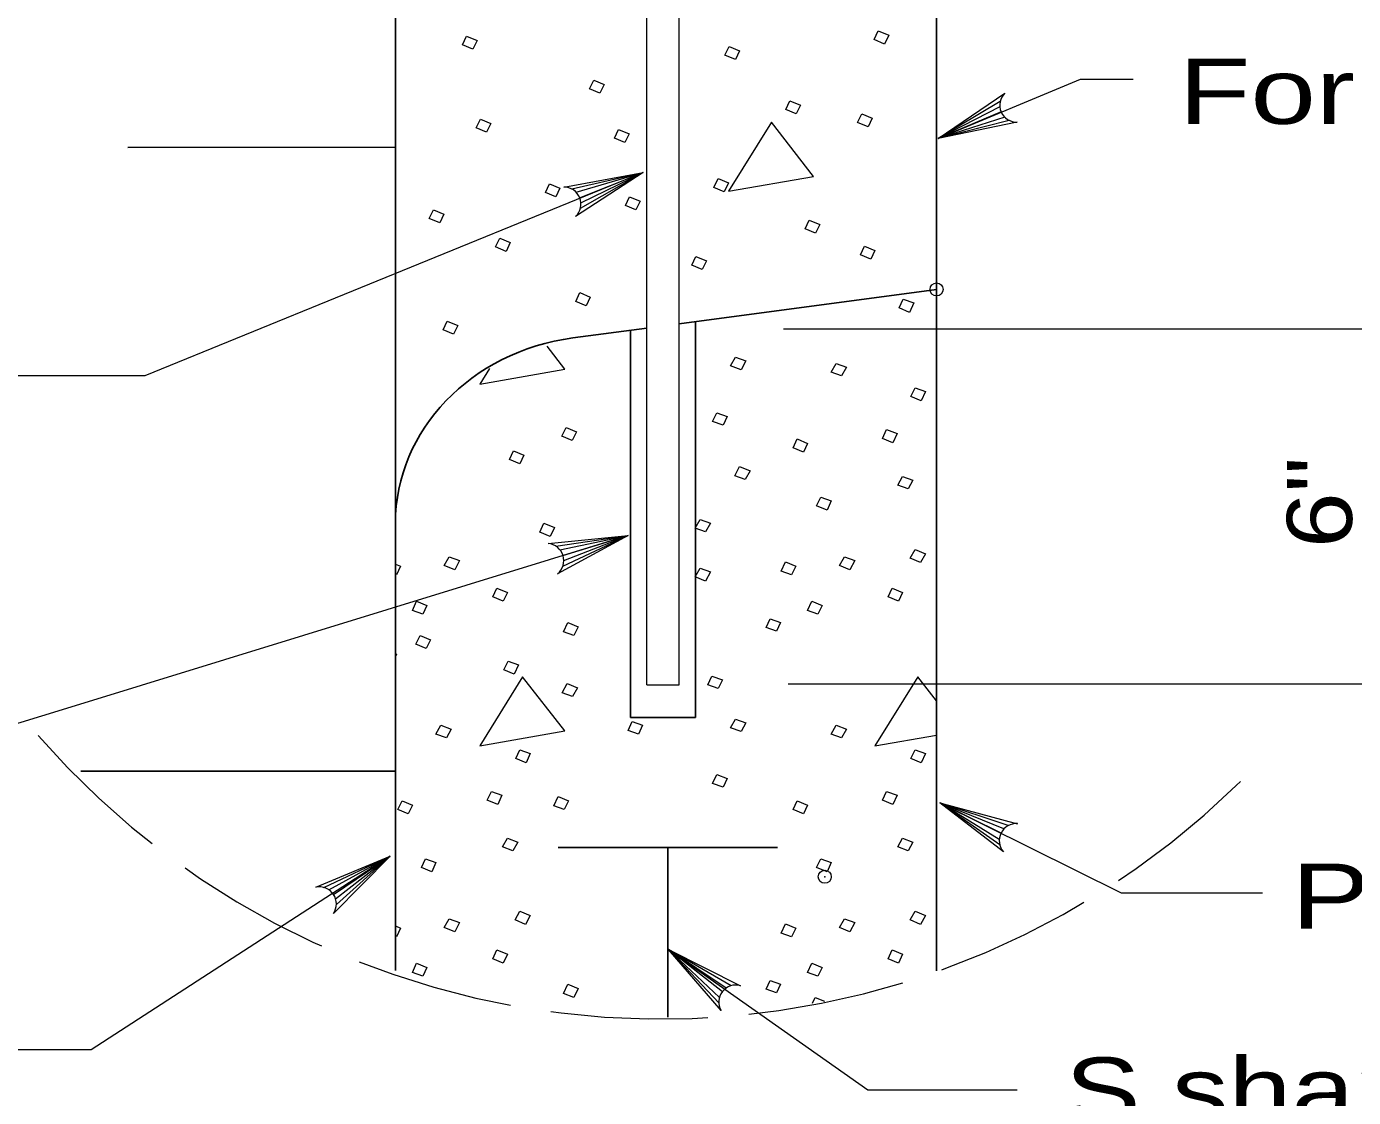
# Model space of a CAD drawing. Extents: x -1431.2 to -1397.2, y -1045.1 to -1001.1.
# Drawn here: x -1416.061 to -1412.824, y -1035.128 to -1032.516 of the extents above; entities that cross this region are included whole.
import ezdxf
from ezdxf.enums import TextEntityAlignment as Align

# ---------------------------------------------------------------- set-up
doc = ezdxf.new("R2010")
doc.units = 0
doc.header["$LTSCALE"] = 0.064
doc.header["$PDMODE"] = 32
doc.header["$PDSIZE"] = 0.032
doc.linetypes.add('LONG_DASHED', pattern=[7.5, 6, -1.5])
doc.layers.add('1', color=7, linetype='Continuous', lineweight=13)

msp = doc.modelspace()

# ---------------------------------------------------------------- linework, layer by layer
at = {"layer": '1'}
for p, q in [((-1414.54825, -1034.12175), (-1414.54825, -1031.64908)), ((-1414.46883, -1034.12175), (-1414.46883, -1031.64908)), ((-1413.84108, -1032.48925), (-1413.84108, -1033.15717)), ((-1413.68608, -1032.6985), (-1413.83692, -1032.78933)), ((-1413.68675, -1032.71192), (-1413.83692, -1032.78933)), ((-1413.68358, -1032.724), (-1413.83692, -1032.78933)), ((-1413.67458, -1032.73717), (-1413.83692, -1032.78933)), ((-1413.66408, -1032.74492), (-1413.83692, -1032.78933)), ((-1414.73092, -1032.91208), (-1414.55708, -1032.87167)), ((-1414.7205, -1032.92008), (-1414.55708, -1032.87167)), ((-1414.71183, -1032.9335), (-1414.55708, -1032.87167)), ((-1414.70992, -1032.959), (-1414.55708, -1032.87167)), ((-1414.70892, -1032.94558), (-1414.55708, -1032.87167)), ((-1414.21442, -1033.2535), (-1412.70433, -1033.2535)), ((-1414.59308, -1033.75767), (-1415.974, -1034.18242)), ((-1414.76967, -1033.78342), (-1414.59308, -1033.75767)), ((-1414.76, -1033.79225), (-1414.59308, -1033.75767)), ((-1414.75267, -1033.83192), (-1414.59308, -1033.75767)), ((-1414.75242, -1033.80633), (-1414.59308, -1033.75767)), ((-1414.75058, -1033.81867), (-1414.59308, -1033.75767)), ((-1413.84108, -1034.16075), (-1413.88692, -1034.10183)), ((-1414.54825, -1034.12175), (-1414.46883, -1034.12175)), ((-1414.20317, -1034.119), (-1412.70433, -1034.119)), ((-1413.68392, -1034.48342), (-1413.83317, -1034.40933)), ((-1413.68817, -1034.49883), (-1413.83317, -1034.40933)), ((-1413.68717, -1034.51192), (-1413.83317, -1034.40933)), ((-1413.67683, -1034.47317), (-1413.83317, -1034.40933)), ((-1413.66617, -1034.465), (-1413.83317, -1034.40933)), ((-1415.33558, -1034.616), (-1415.17425, -1034.53983)), ((-1415.32375, -1034.62167), (-1415.17425, -1034.53983)), ((-1415.31242, -1034.63292), (-1415.17425, -1034.53983)), ((-1415.30708, -1034.64417), (-1415.17425, -1034.53983)), ((-1415.30517, -1034.6575), (-1415.17425, -1034.53983)), ((-1414.36367, -1034.87025), (-1414.495, -1034.76767)), ((-1414.37092, -1034.8845), (-1414.495, -1034.76767)), ((-1414.37258, -1034.8975), (-1414.495, -1034.76767)), ((-1414.35467, -1034.86167), (-1414.495, -1034.76767)), ((-1414.34258, -1034.85575), (-1414.495, -1034.76767)), ((-1414.14392, -1034.89825), (-1414.13717, -1034.88408)), ((-1414.13717, -1034.88408), (-1414.1145, -1034.89358))]:
    msp.add_line(p, q, dxfattribs=at)
at = {"layer": '1', "lineweight": 25}
for p, q in [((-1415.16117, -1033.72717), (-1415.16117, -1032.48925)), ((-1413.84108, -1032.48925), (-1413.84108, -1033.71067)), ((-1415.16083, -1032.81017), (-1415.814, -1032.81083)), ((-1413.84108, -1033.15717), (-1414.46883, -1033.24092)), ((-1413.84108, -1034.81967), (-1413.84108, -1033.15717)), ((-1414.42917, -1034.20117), (-1414.42917, -1033.23558)), ((-1414.54825, -1033.2515), (-1414.72825, -1033.27542)), ((-1414.58792, -1034.20117), (-1414.58792, -1033.25675)), ((-1415.16117, -1033.72717), (-1415.16117, -1034.81825)), ((-1414.58792, -1034.20117), (-1414.42917, -1034.20117)), ((-1415.92817, -1034.33242), (-1415.16117, -1034.33242)), ((-1414.76392, -1034.51867), (-1414.229, -1034.51867)), ((-1414.49642, -1034.51867), (-1414.49642, -1034.93208))]:
    msp.add_line(p, q, dxfattribs=at)
at = {"layer": '1'}
for points in [[(-1413.98325, -1032.5265), (-1413.95783, -1032.53717), (-1413.968, -1032.5585), (-1413.99342, -1032.54783)], [(-1414.98758, -1032.53917), (-1414.96217, -1032.54983), (-1414.97233, -1032.57108), (-1414.99775, -1032.5605)], [(-1414.34725, -1032.56442), (-1414.32183, -1032.57508), (-1414.332, -1032.59642), (-1414.35733, -1032.58575)], [(-1414.6775, -1032.64667), (-1414.65208, -1032.65725), (-1414.66225, -1032.67858), (-1414.68767, -1032.66792)], [(-1414.19892, -1032.69717), (-1414.1735, -1032.70783), (-1414.18367, -1032.72917), (-1414.20908, -1032.7185)], [(-1414.95383, -1032.7415), (-1414.9285, -1032.75208), (-1414.93867, -1032.77342), (-1414.964, -1032.76275)], [(-1414.24417, -1032.74892), (-1414.349, -1032.91783), (-1414.141, -1032.88133)], [(-1414.02367, -1032.72883), (-1413.99825, -1032.7395), (-1414.00842, -1032.76075), (-1414.03383, -1032.75008)], [(-1414.61683, -1032.76675), (-1414.59142, -1032.77742), (-1414.60158, -1032.79867), (-1414.627, -1032.78808)], [(-1414.78533, -1032.8995), (-1414.75992, -1032.91017), (-1414.77008, -1032.9315), (-1414.7955, -1032.92083)], [(-1414.37417, -1032.88692), (-1414.34875, -1032.8975), (-1414.35892, -1032.91883), (-1414.38433, -1032.90817)], [(-1414.58983, -1032.93108), (-1414.5645, -1032.94175), (-1414.57467, -1032.96308), (-1414.6, -1032.95242)], [(-1415.06842, -1032.96275), (-1415.04308, -1032.97333), (-1415.05325, -1032.99467), (-1415.07858, -1032.984)], [(-1414.15175, -1032.988), (-1414.12633, -1032.99867), (-1414.1365, -1033.02), (-1414.16192, -1033.00933)], [(-1414.90667, -1033.03225), (-1414.88125, -1033.04292), (-1414.89142, -1033.06425), (-1414.91683, -1033.05358)], [(-1414.42808, -1033.0765), (-1414.40267, -1033.08717), (-1414.41283, -1033.1085), (-1414.43825, -1033.09783)], [(-1414.01692, -1033.05125), (-1413.9915, -1033.06192), (-1414.00167, -1033.08317), (-1414.02708, -1033.07258)], [(-1414.71117, -1033.165), (-1414.68583, -1033.17567), (-1414.696, -1033.197), (-1414.72133, -1033.18633)], [(-1413.92242, -1033.18108), (-1413.897, -1033.19025), (-1413.90717, -1033.21308), (-1413.9325, -1033.20242)], [(-1415.03475, -1033.23458), (-1415.00933, -1033.24525), (-1415.0195, -1033.2665), (-1415.04492, -1033.25592)], [(-1414.33167, -1033.32267), (-1414.30625, -1033.33175), (-1414.31817, -1033.35308), (-1414.3435, -1033.34392)], [(-1414.08642, -1033.33783), (-1414.06108, -1033.347), (-1414.07292, -1033.36833), (-1414.09825, -1033.35917)], [(-1413.89367, -1033.39717), (-1413.86825, -1033.40633), (-1413.87842, -1033.42917), (-1413.90375, -1033.4185)], [(-1414.37733, -1033.45808), (-1414.35192, -1033.46717), (-1414.36208, -1033.4885), (-1414.3875, -1033.47942)], [(-1414.74492, -1033.49375), (-1414.7195, -1033.50442), (-1414.72967, -1033.52575), (-1414.75508, -1033.51508)], [(-1413.963, -1033.49917), (-1413.93758, -1033.50833), (-1413.94775, -1033.53117), (-1413.97317, -1033.5205)], [(-1414.18117, -1033.522), (-1414.15575, -1033.53267), (-1414.16592, -1033.55392), (-1414.19125, -1033.54333)], [(-1414.873, -1033.55067), (-1414.84758, -1033.56133), (-1414.85775, -1033.58267), (-1414.88308, -1033.572)], [(-1414.3215, -1033.58892), (-1414.29617, -1033.59958), (-1414.308, -1033.62092), (-1414.33333, -1033.61183)], [(-1413.92408, -1033.61333), (-1413.89875, -1033.62242), (-1413.91058, -1033.64375), (-1413.93592, -1033.63458)], [(-1414.12367, -1033.66358), (-1414.09825, -1033.67267), (-1414.10842, -1033.6955), (-1414.13375, -1033.68483)], [(-1414.79883, -1033.72767), (-1414.77342, -1033.73833), (-1414.78358, -1033.75967), (-1414.809, -1033.749)], [(-1414.41792, -1033.71833), (-1414.3925, -1033.7275), (-1414.40442, -1033.74875), (-1414.42975, -1033.73967)], [(-1413.89367, -1033.79133), (-1413.86825, -1033.802), (-1413.88008, -1033.82333), (-1413.9055, -1033.81267)], [(-1415.03008, -1033.80958), (-1415.00475, -1033.81875), (-1415.01658, -1033.84158), (-1415.04192, -1033.831)], [(-1414.20992, -1033.82183), (-1414.1845, -1033.83242), (-1414.19467, -1033.85375), (-1414.22008, -1033.84467)], [(-1414.06617, -1033.80958), (-1414.04075, -1033.81875), (-1414.05258, -1033.84158), (-1414.078, -1033.831)], [(-1414.41792, -1033.837), (-1414.3925, -1033.84617), (-1414.40442, -1033.869), (-1414.42975, -1033.85833)], [(-1414.91342, -1033.88575), (-1414.888, -1033.89642), (-1414.89817, -1033.91767), (-1414.92358, -1033.90708)], [(-1413.94942, -1033.88575), (-1413.92408, -1033.89642), (-1413.93425, -1033.91767), (-1413.95958, -1033.90708)], [(-1415.10958, -1033.91767), (-1415.08425, -1033.92833), (-1415.09433, -1033.94967), (-1415.11975, -1033.9405)], [(-1414.14558, -1033.91767), (-1414.12025, -1033.92833), (-1414.13042, -1033.94967), (-1414.15575, -1033.9405)], [(-1414.74092, -1033.96942), (-1414.71558, -1033.98008), (-1414.72567, -1034.00142), (-1414.75108, -1033.99225)], [(-1414.24708, -1033.96033), (-1414.22175, -1033.96942), (-1414.23192, -1033.99075), (-1414.25725, -1033.98158)], [(-1415.10117, -1034.00142), (-1415.07575, -1034.012), (-1415.08592, -1034.03333), (-1415.11125, -1034.02267)], [(-1414.88633, -1034.06375), (-1414.861, -1034.07292), (-1414.87117, -1034.09575), (-1414.8965, -1034.08508)], [(-1414.85083, -1034.10183), (-1414.95567, -1034.27075), (-1414.74767, -1034.23425)], [(-1414.38917, -1034.10033), (-1414.36375, -1034.10942), (-1414.37392, -1034.13075), (-1414.39925, -1034.12158)], [(-1414.74258, -1034.11858), (-1414.71725, -1034.12925), (-1414.72908, -1034.1505), (-1414.75442, -1034.14142)], [(-1414.58367, -1034.21142), (-1414.55825, -1034.2205), (-1414.56842, -1034.24183), (-1414.59375, -1034.23275)], [(-1414.33167, -1034.20533), (-1414.30625, -1034.2145), (-1414.31817, -1034.23575), (-1414.3435, -1034.22667)], [(-1415.05042, -1034.2205), (-1415.025, -1034.22967), (-1415.03683, -1034.251), (-1415.06225, -1034.24183)], [(-1414.08642, -1034.2205), (-1414.06108, -1034.22967), (-1414.07292, -1034.251), (-1414.09825, -1034.24183)], [(-1414.85758, -1034.27992), (-1414.83225, -1034.289), (-1414.84242, -1034.31183), (-1414.86775, -1034.30125)], [(-1413.89367, -1034.27992), (-1413.86825, -1034.289), (-1413.87842, -1034.31183), (-1413.90375, -1034.30125)], [(-1414.37733, -1034.34075), (-1414.35192, -1034.34992), (-1414.36208, -1034.37125), (-1414.3875, -1034.36208)], [(-1415.14508, -1034.40467), (-1415.11975, -1034.41533), (-1415.12992, -1034.43667), (-1415.15525, -1034.426)], [(-1414.92692, -1034.38183), (-1414.90158, -1034.391), (-1414.91175, -1034.41383), (-1414.93708, -1034.40317)], [(-1414.76458, -1034.394), (-1414.73925, -1034.40467), (-1414.74933, -1034.426), (-1414.77475, -1034.41692)], [(-1414.18117, -1034.40467), (-1414.15575, -1034.41533), (-1414.16592, -1034.43667), (-1414.19125, -1034.426)], [(-1413.963, -1034.38183), (-1413.93758, -1034.391), (-1413.94775, -1034.41383), (-1413.97317, -1034.40317)], [(-1414.888, -1034.496), (-1414.86267, -1034.50517), (-1414.8745, -1034.52642), (-1414.89983, -1034.51733)], [(-1413.92408, -1034.496), (-1413.89875, -1034.50517), (-1413.91058, -1034.52642), (-1413.93592, -1034.51733)], [(-1415.08758, -1034.54625), (-1415.06225, -1034.55533), (-1415.07242, -1034.57817), (-1415.09775, -1034.5675)], [(-1414.12367, -1034.54625), (-1414.09825, -1034.55533), (-1414.10842, -1034.57817), (-1414.13375, -1034.5675)], [(-1415.03008, -1034.69233), (-1415.00475, -1034.70142), (-1415.01658, -1034.72425), (-1415.04192, -1034.71367)], [(-1414.85758, -1034.67408), (-1414.83225, -1034.68475), (-1414.84408, -1034.706), (-1414.86942, -1034.69533)], [(-1414.06617, -1034.69233), (-1414.04075, -1034.70142), (-1414.05258, -1034.72425), (-1414.078, -1034.71367)], [(-1413.89367, -1034.67408), (-1413.86825, -1034.68475), (-1413.88008, -1034.706), (-1413.9055, -1034.69533)], [(-1414.20992, -1034.7045), (-1414.1845, -1034.71517), (-1414.19467, -1034.73642), (-1414.22008, -1034.72733)], [(-1414.91342, -1034.76842), (-1414.888, -1034.77908), (-1414.89817, -1034.80042), (-1414.92358, -1034.78975)], [(-1413.94942, -1034.76842), (-1413.92408, -1034.77908), (-1413.93425, -1034.80042), (-1413.95958, -1034.78975)], [(-1415.10958, -1034.80042), (-1415.08425, -1034.811), (-1415.09433, -1034.83233), (-1415.11975, -1034.82317)], [(-1414.14558, -1034.80042), (-1414.12025, -1034.811), (-1414.13042, -1034.83233), (-1414.15575, -1034.82317)], [(-1414.74092, -1034.85208), (-1414.71558, -1034.86275), (-1414.72567, -1034.88408), (-1414.75108, -1034.875)], [(-1414.24708, -1034.843), (-1414.22175, -1034.85208), (-1414.23192, -1034.87342), (-1414.25725, -1034.86433)]]:
    msp.add_lwpolyline(points, close=True, dxfattribs=at)
for points in [[(-1413.83692, -1032.78933), (-1413.49033, -1032.64383), (-1413.3615, -1032.64383)], [(-1413.64467, -1032.74925), (-1413.83692, -1032.78933), (-1413.67483, -1032.67833)], [(-1414.55708, -1032.87167), (-1415.77233, -1033.36775), (-1416.53258, -1033.36775)], [(-1414.75017, -1032.90733), (-1414.55708, -1032.87167), (-1414.72167, -1032.97892)], [(-1414.932, -1033.34992), (-1414.95567, -1033.38808), (-1414.74767, -1033.35158), (-1414.79117, -1033.29567)], [(-1414.7885, -1033.77708), (-1414.59308, -1033.75767), (-1414.766, -1033.85075)], [(-1415.16117, -1033.82717), (-1415.1485, -1033.83242), (-1415.15858, -1033.85375), (-1415.16117, -1033.85283)], [(-1415.16117, -1034.046), (-1415.15858, -1034.04708), (-1415.16117, -1034.05242)], [(-1413.88692, -1034.10183), (-1413.99175, -1034.27075), (-1413.84108, -1034.24425)], [(-1415.974, -1034.18242), (-1416.26642, -1034.27233), (-1416.59033, -1034.27233)], [(-1413.67783, -1034.52942), (-1413.83317, -1034.40933), (-1413.64358, -1034.4605)], [(-1413.83317, -1034.40933), (-1413.39108, -1034.62883), (-1413.0465, -1034.62883)], [(-1415.17425, -1034.53983), (-1415.903, -1035.01233), (-1416.26283, -1035.01233)], [(-1415.3555, -1034.6155), (-1415.17425, -1034.53983), (-1415.31242, -1034.67942)], [(-1415.16117, -1034.70983), (-1415.1485, -1034.71517), (-1415.15858, -1034.73642), (-1415.16117, -1034.73558)], [(-1414.495, -1034.76767), (-1414.00917, -1035.10942), (-1413.64483, -1035.10942)], [(-1414.367, -1034.91658), (-1414.495, -1034.76767), (-1414.31958, -1034.85592)]]:
    msp.add_lwpolyline(points, dxfattribs=at)
at = {"layer": '1', "linetype": 'LONG_DASHED'}
for start, end in [(35.13019, 188.17384), (221.04369, 317.21699)]:
    msp.add_arc((-1414.51372, -1032.92267), 2.01436, start, end, dxfattribs=at)
at = {"layer": '1'}
for centre, start, end in [((-1413.64544, -1032.70765), 135.17311, 270.99923), ((-1414.75034, -1032.94894), 313.86861, 89.69474), ((-1414.7921, -1033.81853), 309.08186, 84.90799), ((-1413.64674, -1034.50183), 85.68151, 221.50764), ((-1415.34682, -1034.65617), 326.05694, 101.88306), ((-1414.33098, -1034.89577), 74.08718, 209.91331)]:
    msp.add_arc(centre, 0.04156, start, end, dxfattribs=at)
at = {"layer": '1', "lineweight": 25}
msp.add_ellipse((-1414.65382, -1033.72714), major_axis=(-0.50735, 0), ratio=0.899905, start_param=4.859526, end_param=6.2831853, dxfattribs=at)
at = {"layer": '1'}
for p in [(-1413.84108, -1033.15717), (-1414.114, -1034.58983)]:
    msp.add_point(p, dxfattribs=at)

# ---------------------------------------------------------------- texts
for s, width, p in [('Formed Blockout', 1.35, (-1413.25058, -1032.75325)), ('Precast Trough', 1.35, (-1412.97567, -1034.71683)), ('S shape beam', 1.3, (-1413.52792, -1035.18958))]:
    msp.add_text(s, height=0.1588, dxfattribs=dict(at, width=width)).set_placement(p)
at = {"layer": '1', "width": 1.15}
msp.add_text('6"', height=0.1588, rotation=90, dxfattribs=at).set_placement((-1412.82792, -1033.67679), align=Align.CENTER)

doc.saveas('drawing.dxf')
